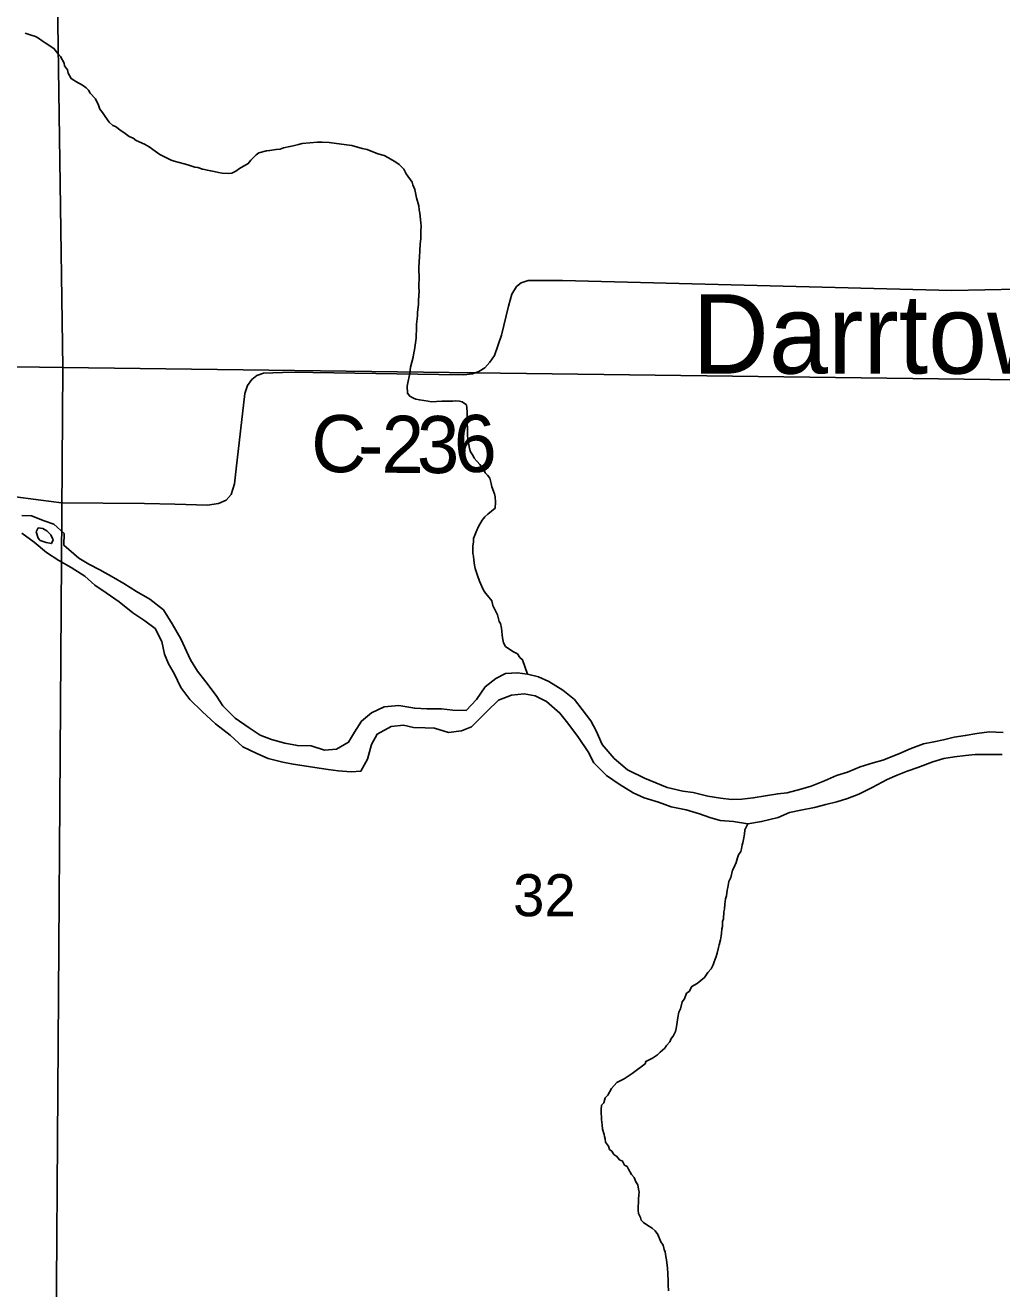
# Model space of a CAD drawing. Extents: x 0 to 34, y 0 to 22.
# Drawn here: x 6.971 to 7.942, y 17.741 to 18.998 of the extents above; entities that cross this region are included whole.
import ezdxf

# ---------------------------------------------------------------- set-up
doc = ezdxf.new("R2010")
doc.units = 0
for name, color, linetype in [('GM_X_County_Road', 7, 'Continuous'), ('GM_X_County_Road_Text', 7, 'Continuous'), ('GM_X_Major_River', 7, 'Continuous'), ('GM_X_Minor_River', 7, 'Continuous'), ('GM_X_Section', 7, 'Continuous'), ('GM_X_Section_Text', 7, 'Continuous'), ('GM_X_Unincorporated_Text', 7, 'Continuous')]:
    doc.layers.add(name, color=color, linetype=linetype)

msp = doc.modelspace()

# ---------------------------------------------------------------- linework, layer by layer
at = {"layer": 'GM_X_County_Road'}
msp.add_lwpolyline([(6.9558, 18.5295), (6.9862, 18.5256), (7.0067, 18.523), (7.0891, 18.5221), (7.1194, 18.5216), (7.152, 18.5206), (7.1629, 18.5221), (7.1705, 18.5254), (7.1754, 18.5312), (7.1787, 18.5418), (7.1806, 18.5567), (7.1892, 18.6318), (7.1917, 18.6396), (7.196, 18.6455), (7.2011, 18.6495), (7.2077, 18.6518), (7.2358, 18.6528), (7.3822, 18.6506), (7.407, 18.6504), (7.4157, 18.6514), (7.422, 18.6537), (7.4278, 18.6573), (7.433, 18.663), (7.4377, 18.6696), (7.4445, 18.6897), (7.4516, 18.7185), (7.4549, 18.7304), (7.4596, 18.738), (7.4642, 18.7417), (7.471, 18.744), (7.5052, 18.7441), (7.8928, 18.7341), (7.9585, 18.7356)], dxfattribs=at)
at = {"layer": 'GM_X_Major_River'}
for points in [[(7.2682, 18.2768), (7.255, 18.2812), (7.2414, 18.2814), (7.2289, 18.2839), (7.2157, 18.2876), (7.2044, 18.2916), (7.1935, 18.299), (7.1796, 18.3087), (7.1673, 18.3211), (7.1607, 18.3311), (7.1503, 18.3449), (7.1421, 18.3553), (7.1351, 18.3668), (7.1253, 18.3875), (7.1168, 18.4025), (7.108, 18.4163), (7.0945, 18.4272), (7.0814, 18.4346), (7.0686, 18.4428), (7.0585, 18.4487), (7.0449, 18.4561), (7.0337, 18.462), (7.0239, 18.4679), (7.009, 18.4807), (7.0092, 18.4925), (6.9991, 18.5018), (6.9893, 18.505), (6.9769, 18.5101), (6.967, 18.5103)], [(6.9671, 18.4928), (6.9794, 18.4839), (6.9917, 18.4734), (7.0041, 18.4656), (7.0161, 18.4585), (7.03, 18.4499), (7.0397, 18.441), (7.051, 18.4332), (7.0641, 18.4243), (7.0776, 18.4134), (7.0896, 18.4056), (7.0997, 18.3978), (7.1066, 18.3848), (7.1091, 18.3722)], [(6.9984, 18.4862), (6.9959, 18.4912), (6.9921, 18.495), (6.988, 18.4974), (6.9835, 18.4979), (6.9815, 18.4941), (6.9833, 18.4876), (6.9855, 18.4853)], [(6.9855, 18.4853), (6.9915, 18.4833), (6.9965, 18.4824), (6.9984, 18.4862)], [(7.1091, 18.3722), (7.1131, 18.3627), (7.1186, 18.3531), (7.1255, 18.3393), (7.1344, 18.3273), (7.1467, 18.3154), (7.1598, 18.303), (7.1744, 18.2917), (7.1871, 18.2801), (7.201, 18.2734), (7.2123, 18.2686), (7.227, 18.2649), (7.2372, 18.2629), (7.2482, 18.2612), (7.2588, 18.2595), (7.272, 18.2577), (7.2819, 18.2564), (7.2948, 18.2554), (7.3046, 18.256), (7.3113, 18.268), (7.315, 18.2824), (7.3209, 18.2929), (7.3347, 18.3003), (7.3469, 18.3016), (7.3571, 18.2995), (7.3684, 18.2989), (7.3779, 18.2988), (7.3919, 18.2943), (7.4048, 18.296), (7.4148, 18.3), (7.4302, 18.3157), (7.4414, 18.3265), (7.4544, 18.3316), (7.467, 18.3329), (7.4779, 18.3308), (7.4892, 18.3253), (7.5027, 18.3137), (7.5105, 18.3036), (7.5212, 18.2894), (7.5308, 18.2752), (7.5363, 18.2641), (7.549, 18.2517), (7.5617, 18.2431), (7.5756, 18.2345), (7.5865, 18.2294), (7.6009, 18.225), (7.6133, 18.2206), (7.6284, 18.2176), (7.6416, 18.2136), (7.6518, 18.21), (7.662, 18.2068), (7.6753, 18.2058), (7.6896, 18.2036), (7.7033, 18.2057), (7.7197, 18.2099), (7.7312, 18.2147), (7.7423, 18.2171), (7.756, 18.2199), (7.7674, 18.2228), (7.7781, 18.2253), (7.7888, 18.2289), (7.8002, 18.2332), (7.8133, 18.2398), (7.8282, 18.2475), (7.8382, 18.2519), (7.8481, 18.2559), (7.8588, 18.2595), (7.8737, 18.2653), (7.8848, 18.2686), (7.8954, 18.2703), (7.9064, 18.2716), (7.916, 18.2726), (7.9277, 18.2724), (7.9429, 18.2725)], [(7.9437, 18.2945), (7.93, 18.2951), (7.9175, 18.2934), (7.9061, 18.2914), (7.895, 18.2897), (7.8843, 18.2872), (7.8748, 18.2851), (7.8645, 18.283), (7.8512, 18.2783), (7.8401, 18.2732), (7.824, 18.267), (7.8145, 18.2641), (7.8015, 18.2602), (7.7889, 18.2551), (7.7778, 18.2515), (7.7659, 18.2464), (7.7526, 18.2409), (7.7423, 18.238), (7.7289, 18.2345), (7.7194, 18.2335), (7.695, 18.2294), (7.6836, 18.2281), (7.6734, 18.2279), (7.6624, 18.2292), (7.6499, 18.2309), (7.6352, 18.2346), (7.625, 18.2359), (7.6095, 18.2396), (7.5869, 18.2491), (7.5699, 18.2574), (7.5565, 18.2687), (7.5446, 18.2825), (7.5388, 18.2959), (7.5333, 18.3059), (7.5247, 18.3174), (7.5173, 18.3271), (7.5054, 18.3364), (7.4915, 18.345), (7.4813, 18.3497), (7.4704, 18.3526), (7.4605, 18.3539), (7.4484, 18.353), (7.4388, 18.3482), (7.4284, 18.34), (7.4198, 18.3273), (7.4094, 18.3164), (7.3961, 18.3167), (7.3847, 18.318), (7.3703, 18.3179), (7.3582, 18.3185), (7.3423, 18.3214), (7.3278, 18.3201), (7.3152, 18.3139), (7.3052, 18.3057), (7.2981, 18.2948), (7.2923, 18.2847), (7.2804, 18.2777), (7.2682, 18.2768)]]:
    msp.add_lwpolyline(points, dxfattribs=at)
at = {"layer": 'GM_X_Minor_River'}
for points in [[(7.3645, 18.7981), (7.3642, 18.8015), (7.3633, 18.8111), (7.3626, 18.8145), (7.3623, 18.8183), (7.3598, 18.8263), (7.3581, 18.8347), (7.3563, 18.8393), (7.3556, 18.842), (7.3497, 18.8501), (7.3472, 18.8548), (7.3427, 18.8594), (7.3394, 18.8618), (7.3322, 18.8662), (7.3277, 18.8685), (7.3213, 18.8702), (7.3107, 18.8743), (7.3058, 18.8755), (7.2956, 18.8785), (7.2903, 18.879), (7.2729, 18.8813), (7.2661, 18.8818), (7.2615, 18.8816), (7.2462, 18.8804), (7.2424, 18.8794), (7.2371, 18.878), (7.234, 18.8773), (7.2275, 18.876), (7.2241, 18.8749), (7.2202, 18.8746), (7.2137, 18.8733), (7.2107, 18.873), (7.2031, 18.8712), (7.2003, 18.869), (7.1949, 18.8639), (7.1925, 18.8605), (7.1837, 18.8554), (7.1802, 18.8528), (7.176, 18.851), (7.1725, 18.8507), (7.1665, 18.8509), (7.163, 18.8514), (7.1585, 18.8526), (7.1551, 18.8531), (7.1517, 18.8539), (7.149, 18.8544), (7.1468, 18.8548), (7.1422, 18.8564), (7.1392, 18.8569), (7.1324, 18.8593), (7.1286, 18.8602), (7.1188, 18.8627), (7.1158, 18.8639), (7.1045, 18.8695), (7.1, 18.8727), (7.0937, 18.877), (7.0892, 18.8798), (7.0809, 18.8834), (7.0779, 18.8857), (7.0741, 18.8874), (7.0685, 18.8913), (7.0659, 18.8929), (7.0603, 18.8972), (7.0576, 18.8984), (7.0539, 18.9015), (7.0502, 18.9073), (7.0473, 18.9112), (7.0447, 18.9147), (7.0433, 18.9185), (7.0404, 18.925), (7.0352, 18.9305), (7.0334, 18.9336), (7.0311, 18.9359), (7.0274, 18.9386), (7.021, 18.9422), (7.0188, 18.9434), (7.0161, 18.945), (7.0132, 18.9504), (7.0125, 18.9538), (7.0096, 18.9577), (7.0093, 18.9604), (7.0056, 18.9669), (7.003, 18.97), (6.999, 18.975), (6.9903, 18.9806), (6.9873, 18.9826), (6.9836, 18.9853), (6.9806, 18.9869), (6.9764, 18.9881), (6.9704, 18.9902)], [(7.4704, 18.3526), (7.4655, 18.3668), (7.4629, 18.3691), (7.4604, 18.3726), (7.4558, 18.375), (7.4484, 18.3801), (7.4465, 18.3836), (7.4455, 18.3886), (7.4452, 18.3916), (7.4446, 18.3981), (7.4436, 18.4027), (7.4421, 18.405), (7.4407, 18.4115), (7.436, 18.4207), (7.435, 18.4253), (7.4305, 18.4307), (7.4287, 18.433), (7.4265, 18.4361), (7.425, 18.4396), (7.4225, 18.445), (7.4207, 18.4507), (7.4182, 18.4576), (7.4175, 18.461), (7.4169, 18.466), (7.4166, 18.4698), (7.4159, 18.4725), (7.4161, 18.4797), (7.4165, 18.4842), (7.4166, 18.4873), (7.4194, 18.494), (7.4215, 18.4993), (7.4254, 18.5057), (7.4278, 18.509), (7.4309, 18.5116), (7.4382, 18.5175), (7.4384, 18.5236), (7.4381, 18.5289), (7.4374, 18.532), (7.4349, 18.5389), (7.4342, 18.5423), (7.4328, 18.5473), (7.4306, 18.5504), (7.4284, 18.5527), (7.427, 18.5561), (7.4229, 18.5612), (7.4173, 18.5674), (7.4163, 18.5697), (7.4137, 18.5736), (7.4126, 18.577), (7.4109, 18.5858), (7.4107, 18.5907), (7.4107, 18.5942), (7.4102, 18.6044), (7.4104, 18.6132), (7.4101, 18.6173), (7.4098, 18.6204), (7.4053, 18.6235), (7.4027, 18.624), (7.3985, 18.6245), (7.3962, 18.6241), (7.3928, 18.6242), (7.3878, 18.624), (7.3852, 18.624), (7.3745, 18.6235), (7.3715, 18.624), (7.3628, 18.6253), (7.3594, 18.6262), (7.3571, 18.627), (7.3534, 18.629), (7.3508, 18.6321), (7.3505, 18.6389), (7.3514, 18.6423), (7.3531, 18.6503), (7.3536, 18.6548), (7.354, 18.6578), (7.3565, 18.6677), (7.3574, 18.6722), (7.3579, 18.6752), (7.3596, 18.6866), (7.3599, 18.698), (7.36, 18.7006), (7.3605, 18.7059), (7.3609, 18.7093), (7.361, 18.7124), (7.3619, 18.7207), (7.362, 18.7245), (7.3626, 18.7336), (7.3623, 18.737), (7.3626, 18.7484), (7.3623, 18.7541), (7.3624, 18.7575), (7.363, 18.7678), (7.3632, 18.7735), (7.3637, 18.7807), (7.3642, 18.7856), (7.3644, 18.7932), (7.3645, 18.7981)], [(7.6896, 18.2036), (7.6868, 18.1976), (7.6863, 18.1934), (7.6854, 18.1881), (7.6846, 18.1847), (7.6841, 18.1825), (7.6833, 18.1787), (7.6828, 18.176), (7.6805, 18.1727), (7.6793, 18.1697), (7.678, 18.1652), (7.6756, 18.1599), (7.6744, 18.1576), (7.6727, 18.1501), (7.6707, 18.146), (7.6698, 18.1403), (7.669, 18.1376), (7.6685, 18.132), (7.6673, 18.129), (7.6668, 18.1236), (7.6663, 18.1187), (7.6658, 18.1161), (7.6653, 18.1089), (7.6645, 18.1062), (7.6644, 18.1013), (7.6639, 18.099), (7.6634, 18.0945), (7.663, 18.0922), (7.6625, 18.088), (7.6613, 18.0831), (7.6605, 18.0805), (7.6592, 18.0748), (7.6583, 18.0714), (7.6563, 18.0662), (7.6551, 18.0632), (7.6531, 18.0594), (7.65, 18.0557), (7.6465, 18.0508), (7.6391, 18.0446), (7.6341, 18.0417), (7.6313, 18.0368), (7.6286, 18.035), (7.6266, 18.0293), (7.6242, 18.0263), (7.6225, 18.0195), (7.6209, 18.0162), (7.6201, 18.0109), (7.6196, 18.0086), (7.6191, 18.004), (7.6183, 17.9999), (7.6178, 17.9969), (7.6154, 17.9924), (7.6135, 17.9901), (7.6119, 17.9868), (7.6088, 17.983), (7.6072, 17.9804), (7.6025, 17.9764), (7.5998, 17.9738), (7.5948, 17.9705), (7.5882, 17.9672), (7.5874, 17.9649), (7.5746, 17.955), (7.5665, 17.9499), (7.5592, 17.9463), (7.5541, 17.9403), (7.5502, 17.9336), (7.5478, 17.931), (7.5462, 17.9261), (7.5442, 17.9235), (7.5438, 17.9193), (7.5437, 17.9155), (7.544, 17.9121), (7.5439, 17.9094), (7.5446, 17.9041), (7.5452, 17.8999), (7.5466, 17.8946), (7.5469, 17.8923), (7.5477, 17.89), (7.548, 17.8869), (7.5509, 17.8827), (7.552, 17.8796), (7.5542, 17.8777), (7.5564, 17.8746), (7.5594, 17.8726), (7.562, 17.8691), (7.565, 17.8679), (7.5668, 17.864), (7.5695, 17.8625), (7.5709, 17.8598), (7.5738, 17.8548), (7.5764, 17.8517), (7.5782, 17.8474), (7.5801, 17.8443), (7.5807, 17.8402), (7.5814, 17.8375), (7.5813, 17.8341), (7.5809, 17.8303), (7.5806, 17.8193), (7.5809, 17.8158)], [(7.5809, 17.8158), (7.5827, 17.812), (7.5834, 17.8093), (7.5857, 17.807), (7.5901, 17.8038), (7.5946, 17.8011), (7.5976, 17.7987), (7.6002, 17.7948), (7.6031, 17.7876), (7.6053, 17.7845), (7.6063, 17.7799), (7.6074, 17.7776), (7.6081, 17.773), (7.6087, 17.7696), (7.6097, 17.7616), (7.61, 17.7562), (7.6105, 17.7486), (7.6105, 17.7448), (7.6107, 17.7388)]]:
    msp.add_lwpolyline(points, dxfattribs=at)
at = {"layer": 'GM_X_Section'}
for points in [[(6.9929, 19.6861), (7.008, 18.6577), (6.0336, 18.6715), (6.0653, 19.7127)], [(6.9929, 19.6861), (7.9969, 19.6588), (7.9821, 18.6451), (7.008, 18.6577)], [(6.0336, 18.6715), (7.008, 18.6577), (7.0009, 17.6487), (5.9983, 17.6719)], [(7.008, 18.6577), (7.9821, 18.6451), (7.9657, 17.6264), (7.0384, 17.6474), (7.0009, 17.6487)]]:
    msp.add_lwpolyline(points, close=True, dxfattribs=at)

# ---------------------------------------------------------------- texts
at = {"layer": 'GM_X_County_Road_Text'}
for s, rotation, p in [('C', 359.3872, (7.2548, 18.5537)), ('2', 359.4635, (7.3249, 18.5529)), ('3', 359.7543, (7.3602, 18.5526)), ('6', 2.8117, (7.3985, 18.5525)), ('-', 359.4043, (7.3015, 18.5532))]:
    msp.add_text(s, height=0.0568, rotation=rotation, dxfattribs=at).set_placement(p)
at = {"layer": 'GM_X_Section_Text'}
msp.add_text('32', height=0.04186, rotation=0, dxfattribs=at).set_placement((7.4561, 18.1116))
at = {"layer": 'GM_X_Unincorporated_Text'}
msp.add_text('Darrtown', height=0.07898, rotation=0, dxfattribs=at).set_placement((7.6344, 18.6515))

doc.saveas('drawing.dxf')
